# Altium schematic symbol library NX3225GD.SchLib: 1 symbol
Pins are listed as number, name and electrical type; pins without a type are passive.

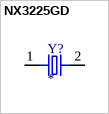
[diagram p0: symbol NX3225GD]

## NX3225GD
designator Y?
8MHz Â±20ppm Crystal 18pF 140 Ohms 2-SMD, No Lead; MP: ABM3-8.000MHZ-D2Y-T; MF: Abracon
footprint NX3225GD
pins: 1, 2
